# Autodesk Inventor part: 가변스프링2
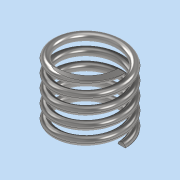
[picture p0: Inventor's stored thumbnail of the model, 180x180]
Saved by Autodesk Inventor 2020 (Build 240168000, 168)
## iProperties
Created: 2021-10
Part Number: 가변스프링2
Material: 스테인레스 스틸
Document SubType Name: Modeling
Designer: user
Density: 8 g/cm^3
Appearance: 반연마
Mass: 6.54924 g
Surface Area: 16.7052 cm^2
Volume: 0.818655 cm^3
Author: user
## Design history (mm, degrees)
sketch "스케치1"
  geometry: L1 (0, 0)-(8.5, 0); L2 (8.5, 0)-(8.5, 17.5); L3 (8.5, 17.5)-(0, 17.5); L4 (0, 17.5)-(0, 0); C1 r 1 at (8.5, 17.5)
  constraints: 8 end point, 2 parallel, 1 centre point, 1 coincident, 1 horizontal, 1 perpendicular
  dimensions: "d0" = 2 diameter of C1; "d1" = 17 diameter of L2 L4; "d2" = 17.5 distance between parallel lines of L1 L3 (derived)
feature "코일1" sketch "스케치1" pitch "d3" = 10; turns "d5" = 5; dims "d4" = 17.5 (= d2), "d6" = 0, angle "d7" = 90 deg, angle "d8" = 90 deg, "d9" = 0, "d10" = 0
sketch "스케치2"
  geometry: L1 (17.5, 11.854)-(0, 11.854); L2 (0, 11.854)-(0, -11.854); L3 (0, -11.854)-(17.5, -11.854); L4 (17.5, -11.854)-(17.5, 11.854); 2 further points
  constraints: 8 end point, 2 parallel, 1 coincident, 1 horizontal, 1 midpoint, 1 perpendicular
  dimensions: "d11" = 17.5 distance between parallel lines of L2 L4 (= d2)
extrude "돌출1" sketch "스케치2" stored distance "d12" = 32.5; taper "d13" = 0 deg
node "솔리드1"
